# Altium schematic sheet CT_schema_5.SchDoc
size 400 x 269 mm
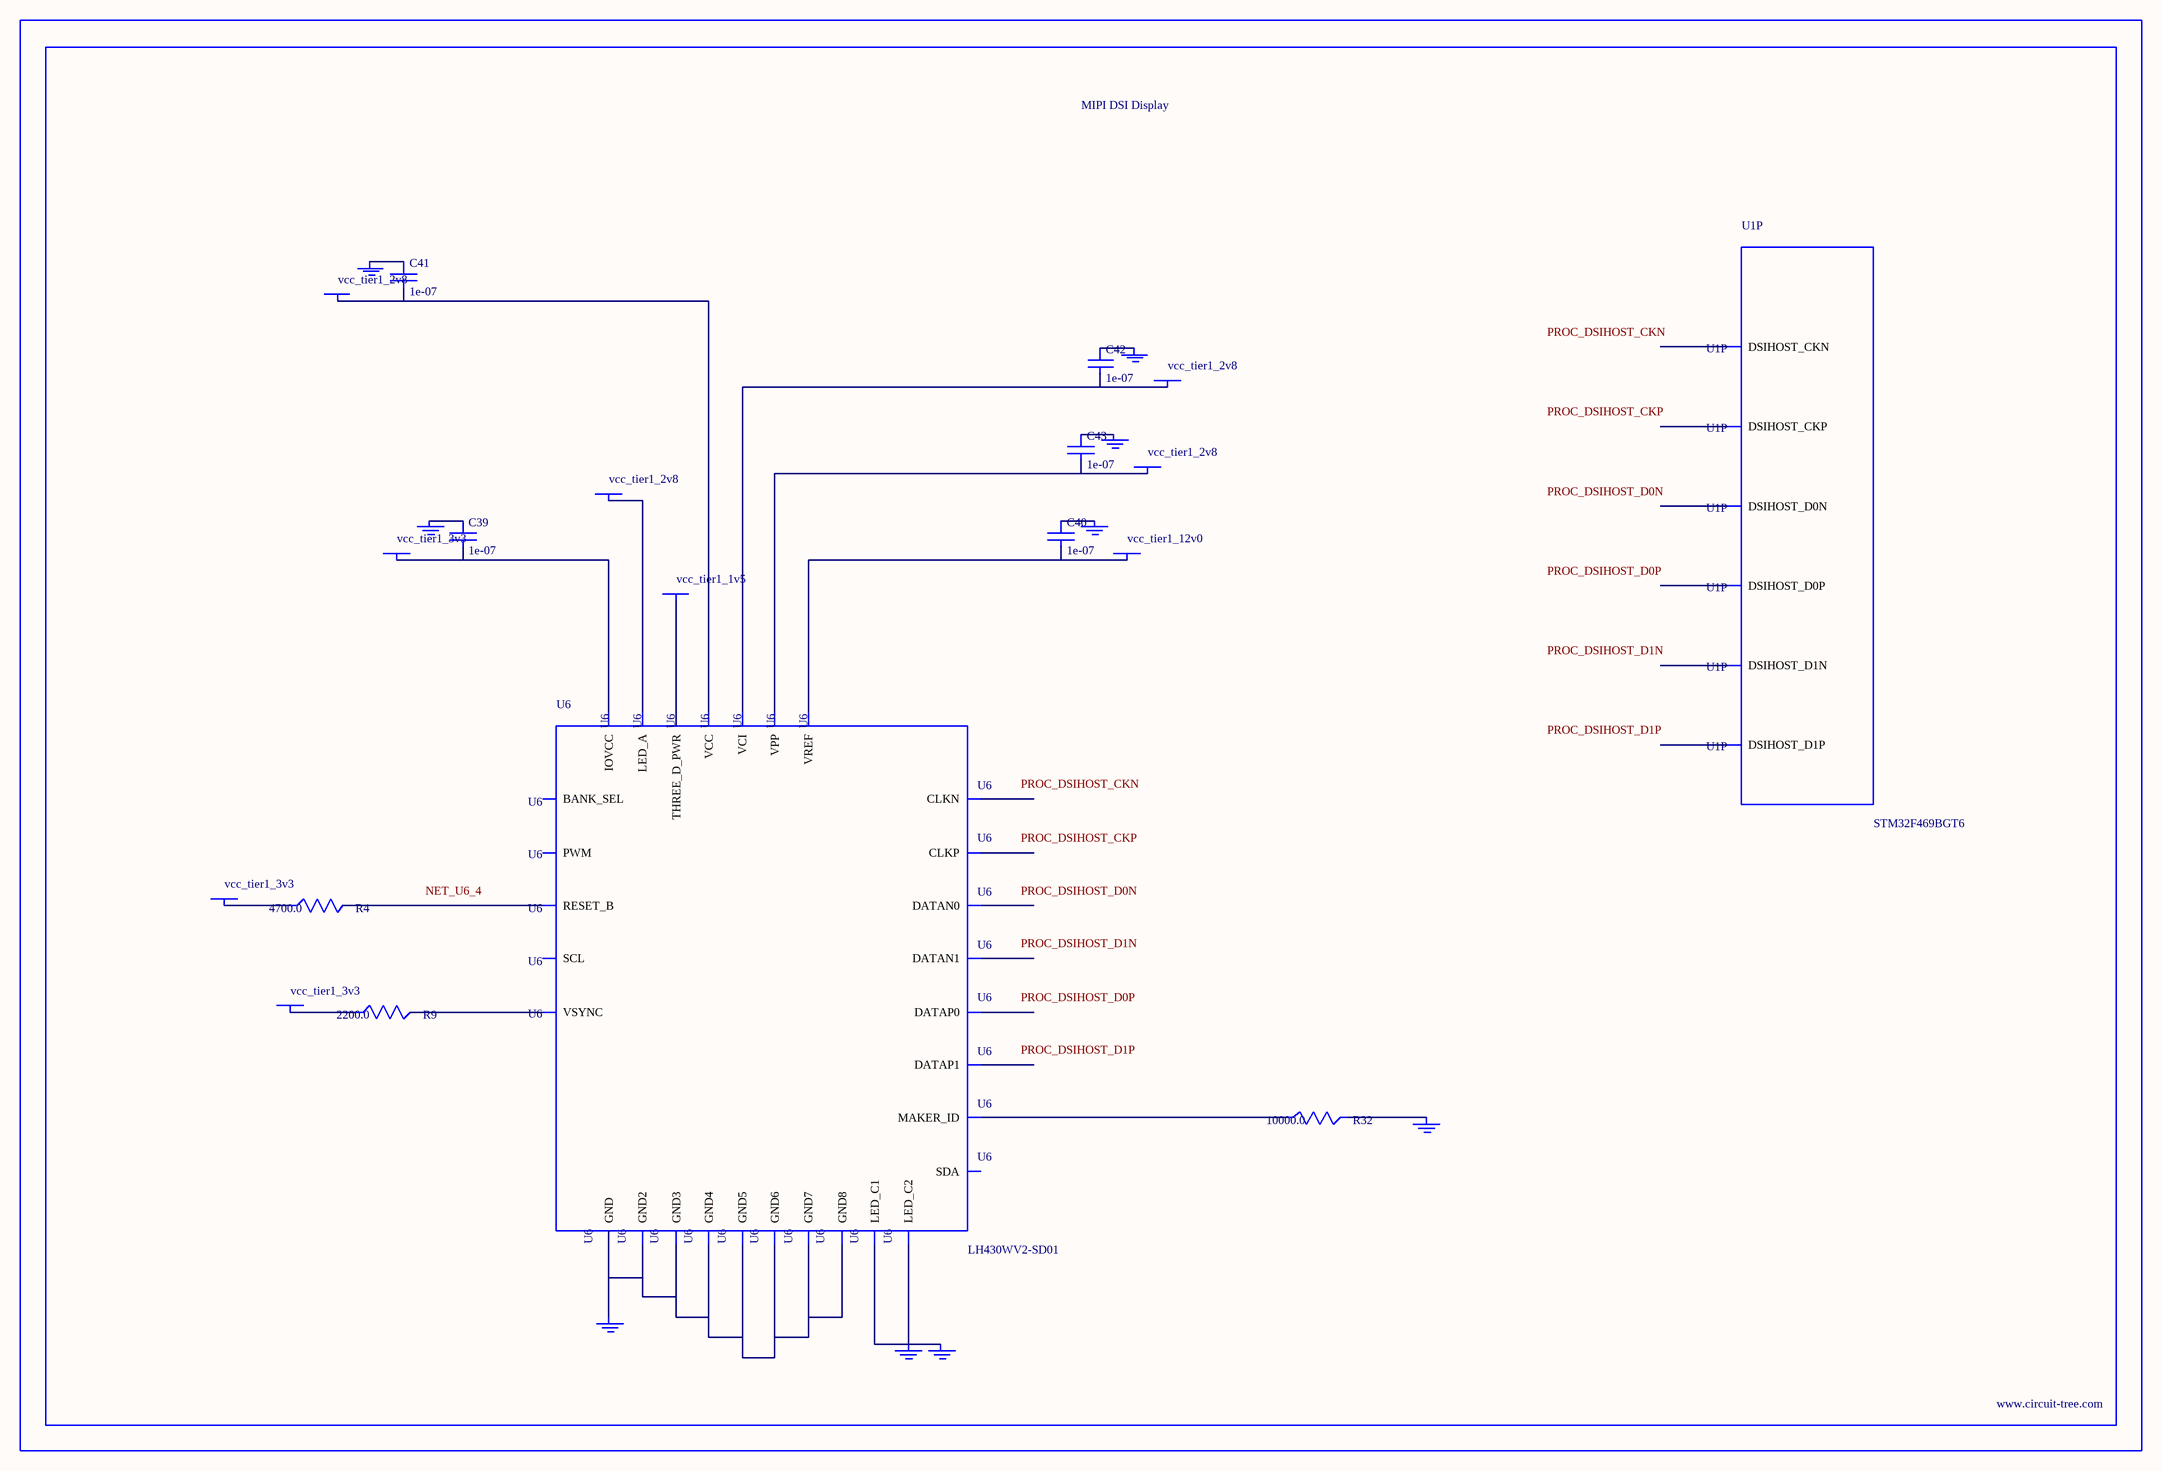
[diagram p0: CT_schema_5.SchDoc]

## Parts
BORDER4  (no value)
C39  1e-07  [C0402]
C40  1e-07  [C0402]
C41  1e-07  [C0402]
C42  1e-07  [C0402]
C43  1e-07  [C0402]
GND_INSTANCE_4_0  (no value)
GND_INSTANCE_4_1  (no value)
GND_INSTANCE_4_2  (no value)
GND_INSTANCE_4_3  (no value)
GND_INSTANCE_4_4  (no value)
GND_INSTANCE_4_5  (no value)
GND_INSTANCE_4_6  (no value)
GND_INSTANCE_4_7  (no value)
GND_INSTANCE_4_8  (no value)
POWER_INSTANCE_4_0  vcc_tier1_3v3
POWER_INSTANCE_4_1  vcc_tier1_2v8
POWER_INSTANCE_4_2  vcc_tier1_2v8
POWER_INSTANCE_4_3  vcc_tier1_2v8
POWER_INSTANCE_4_4  vcc_tier1_2v8
POWER_INSTANCE_4_5  vcc_tier1_12v0
POWER_INSTANCE_4_6  vcc_tier1_3v3
POWER_INSTANCE_4_7  vcc_tier1_3v3
POWER_INSTANCE_4_8  vcc_tier1_1v5
R4  4700.0  [R0603]
R9  2200.0  [R0603]
R32  10000.0  [R0603]
U1  STM32F469BGT6  [LQFP208]  (part P of 16)
U6  LH430WV2-SD01  [LH430WV2-SD01]

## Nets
NetC39_1: C39.1 GND_INSTANCE_4_0.0(GND)
NetC39_2: C39.2 POWER_INSTANCE_4_0.0(PWR) U6.2(IOVCC)
NetC40_1: C40.1 GND_INSTANCE_4_7.0(GND)
NetC40_2: C40.2 POWER_INSTANCE_4_5.0(PWR) U6.30(VREF)
NetC41_1: C41.1 GND_INSTANCE_4_5.0(GND)
NetC41_2: C41.2 POWER_INSTANCE_4_3.0(PWR) U6.22(VCC)
NetC42_1: C42.1 GND_INSTANCE_4_4.0(GND)
NetC42_2: C42.2 POWER_INSTANCE_4_2.0(PWR) U6.21(VCI)
NetC43_1: C43.1 GND_INSTANCE_4_6.0(GND)
NetC43_2: C43.2 POWER_INSTANCE_4_4.0(PWR) U6.23(VPP)
NetGND_INSTANCE_4_1_0: GND_INSTANCE_4_1.0(GND) GND_INSTANCE_4_2.0(GND) U6.17(LED_C1) U6.18(LED_C2)
NetGND_INSTANCE_4_3_0: GND_INSTANCE_4_3.0(GND) R32.2
NetGND_INSTANCE_4_8_0: GND_INSTANCE_4_8.0(GND) U6.1(GND) U6.6(GND2) U6.9(GND3) U6.12(GND4) U6.15(GND5) U6.19(GND6) U6.24(GND7) U6.27(GND8)
NetPOWER_INSTANCE_4_1_0: POWER_INSTANCE_4_1.0(PWR) U6.16(LED_A)
NetPOWER_INSTANCE_4_6_0: POWER_INSTANCE_4_6.0(PWR) R4.1
NetPOWER_INSTANCE_4_7_0: POWER_INSTANCE_4_7.0(PWR) R9.1
NetPOWER_INSTANCE_4_8_0: POWER_INSTANCE_4_8.0(PWR) U6.29(THREE_D_PWR)
NetR4_2: R4.2 U6.4(RESET_B)
NetR9_2: R9.2 U6.5(VSYNC)
NetR32_1: R32.1 U6.20(MAKER_ID)

Not connected (* = marked no-connect by the designer): U1 120(DSIHOST_D0P) 121(DSIHOST_D0N) 123(DSIHOST_CKP) 124(DSIHOST_CKN) 126(DSIHOST_D1P) 127(DSIHOST_D1N); U6 3(PWM) 7(DATAN0) 8(DATAP0) 10(DATAN1) 11(DATAP1) 13(CLKN) 14(CLKP) 25(SCL) 26(SDA) 28(BANK_SEL)

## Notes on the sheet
- Labels drawn without touching a wire or pin: NET_U6_4, PROC_DSIHOST_CKN, PROC_DSIHOST_CKP, PROC_DSIHOST_D0N, PROC_DSIHOST_D0P, PROC_DSIHOST_D1N, PROC_DSIHOST_D1P

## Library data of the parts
BORDER4 = BORDER_PAGE4
C39-C43 = C0402C104K3RACTU
GND_INSTANCE_4_0-GND_INSTANCE_4_8 = GND
POWER_INSTANCE_4_0-POWER_INSTANCE_4_8 = PWR
R4 = RC0603JR-074K7L
R9 = RC0603JR-072K2L
R32 = RC0603JR-0710KL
